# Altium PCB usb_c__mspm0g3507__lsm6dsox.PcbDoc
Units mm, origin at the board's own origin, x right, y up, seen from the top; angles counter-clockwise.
Board outline 68 x 40 mm, 2 copper layers (Top, Bottom), stack 0 mm thick; 37 components, 30 nets, 196 pads, 72 vias.
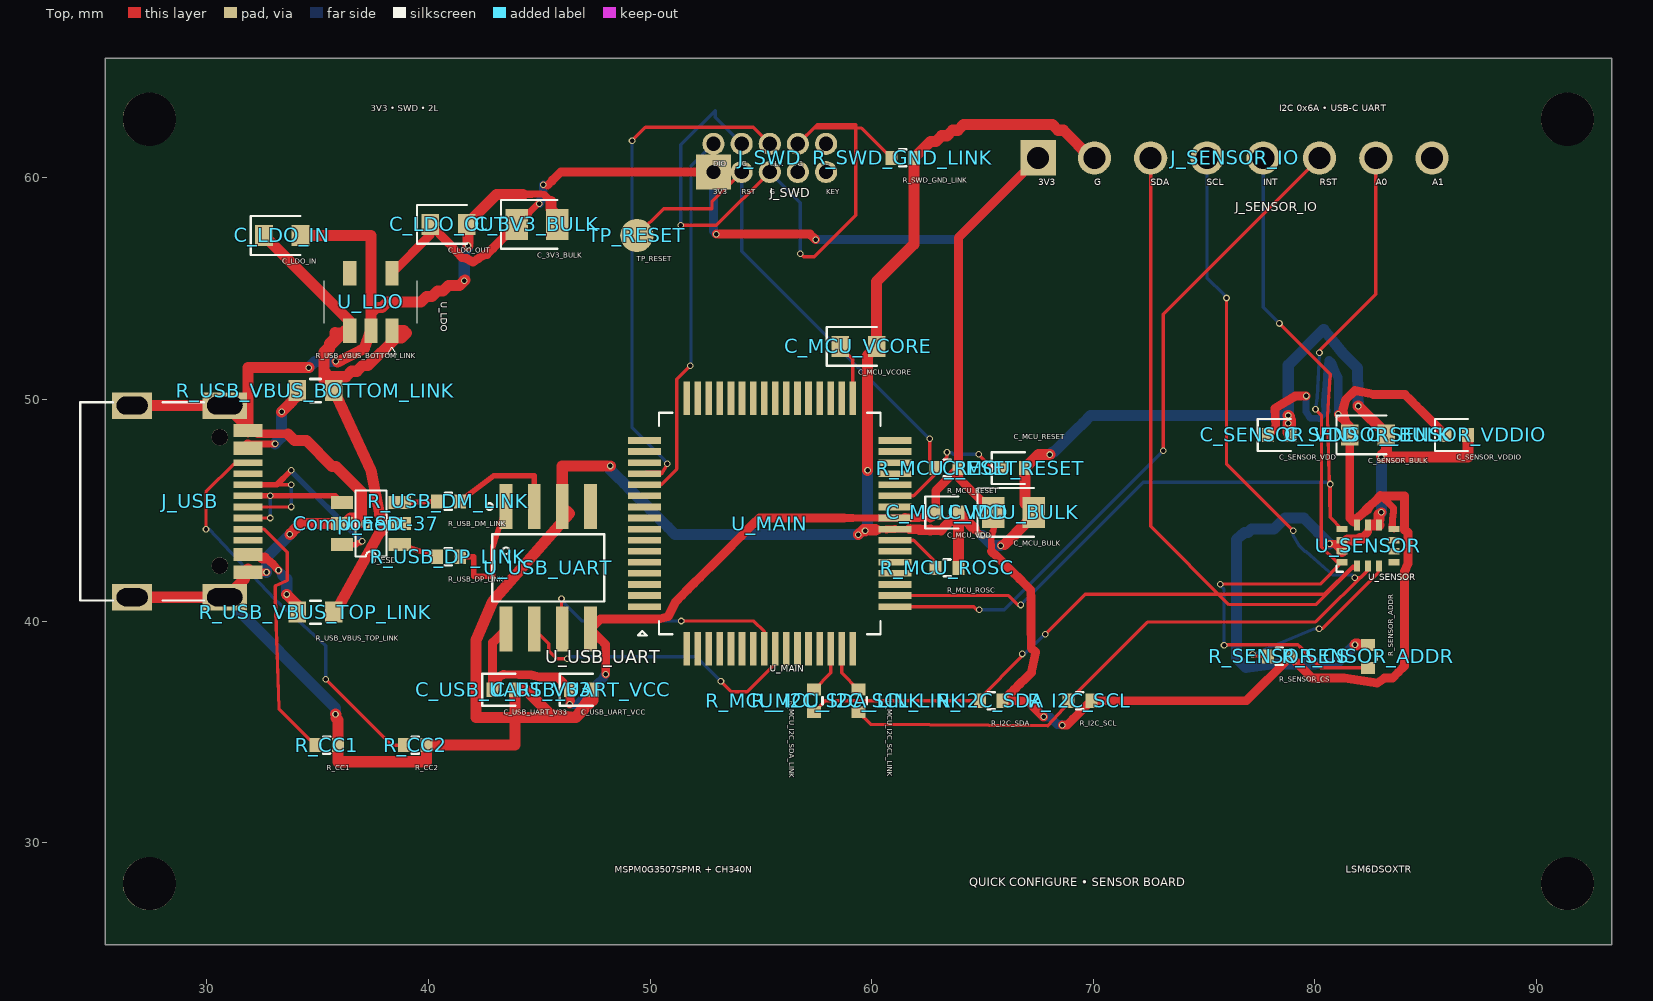
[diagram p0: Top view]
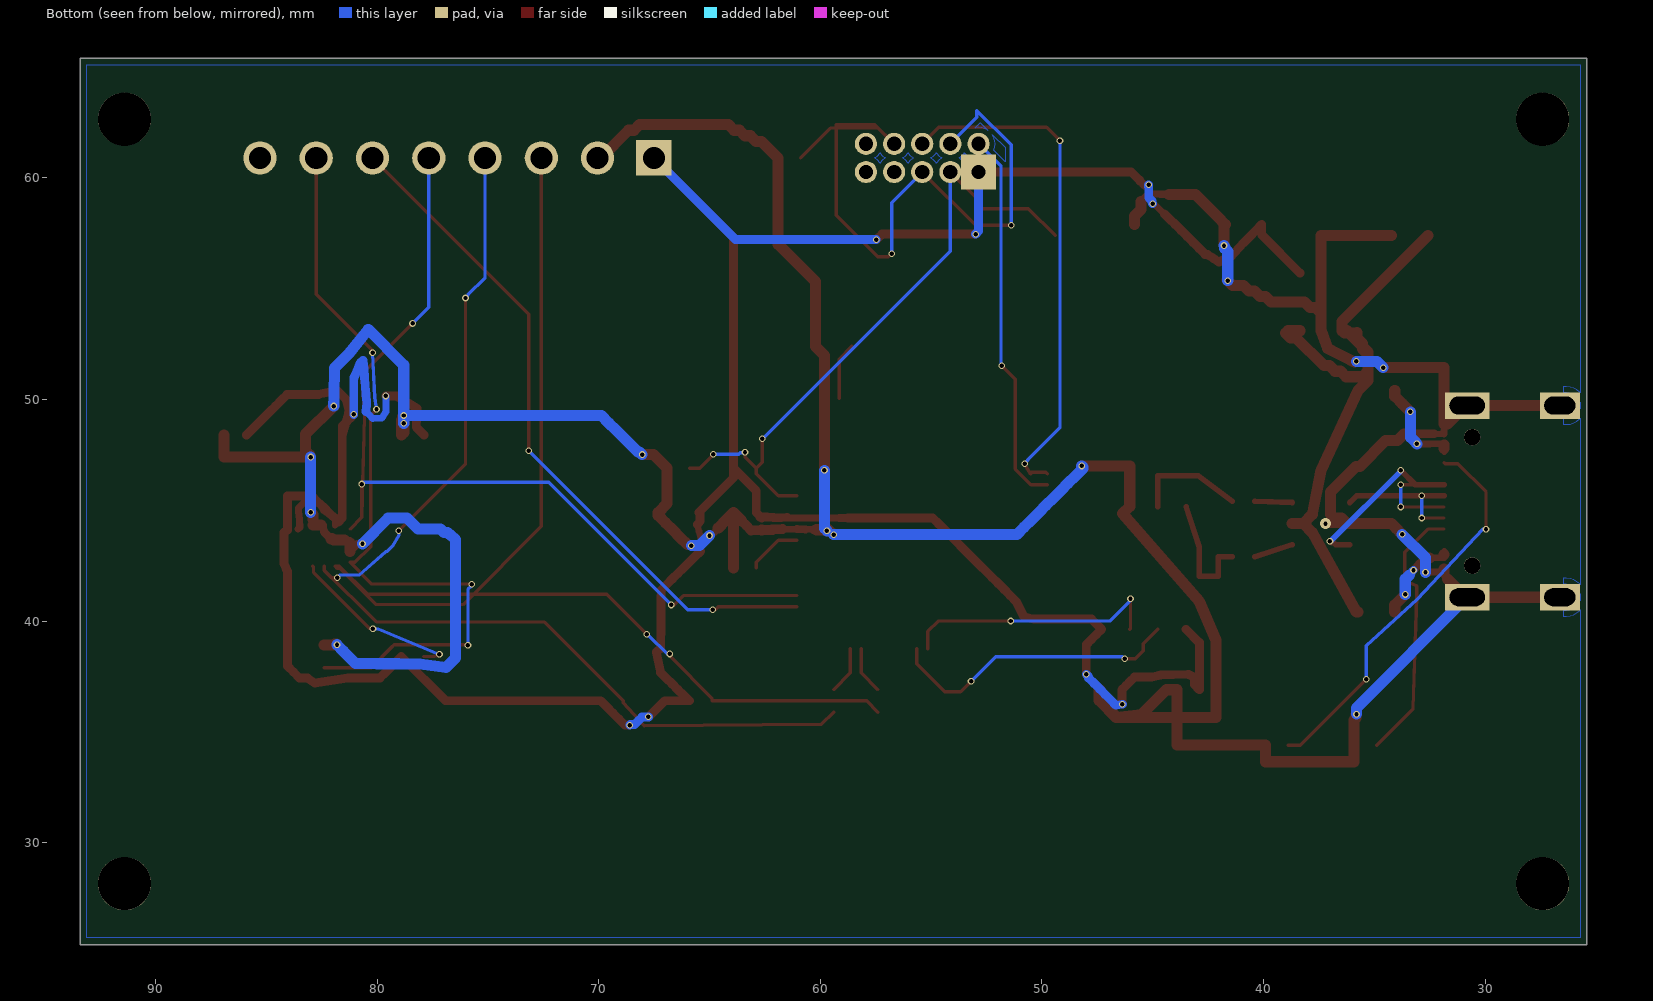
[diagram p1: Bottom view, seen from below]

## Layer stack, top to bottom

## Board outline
25.4,65.4 93.4,65.4 93.4,25.4 25.4,25.4

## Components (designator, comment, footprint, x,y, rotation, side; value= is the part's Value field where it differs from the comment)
C_3V3_BULK "" TSCIRCUIT-2.8500x1.4000mm 44.9,57.9 r0 top
C_LDO_IN "" TSCIRCUIT-2.4500x0.9500mm 33.4,57.4 r0 top
C_LDO_OUT "" TSCIRCUIT-2.4500x0.9500mm 40.9,57.9 r0 top
C_MCU_BULK "" TSCIRCUIT-2.8500x1.4000mm 66.4,44.9 r0 top
C_MCU_RESET "" TSCIRCUIT-1.5600x0.6400mm 66.4,46.9 r0 top
C_MCU_VCORE "" TSCIRCUIT-2.4500x0.9500mm 59.4,52.4 r0 top
C_MCU_VDD "" TSCIRCUIT-1.5600x0.6400mm 63.4,44.9 r0 top
C_SENSOR_BULK "" TSCIRCUIT-2.4500x0.9500mm 82.4,48.4 r0 top
C_SENSOR_VDD "" TSCIRCUIT-1.5600x0.6400mm 78.4,48.4 r0 top
C_SENSOR_VDDIO "" TSCIRCUIT-1.5600x0.6400mm 86.4,48.4 r0 top
C_USB_UART_V33 "" TSCIRCUIT-1.5600x0.6400mm 43.4,36.9 r0 top
C_USB_UART_VCC "" TSCIRCUIT-1.5600x0.6400mm 46.9,36.9 r0 top
Component-37 "" TSCIRCUIT-0.5000x0.5000mm 37.2,44.4 r0 top
J_SENSOR_IO "" TSCIRCUIT-19.2800x1.5000mm 76.4,60.9 r0 top
J_SWD "" TSCIRCUIT-6.0800x2.2700mm 55.4,60.9 r0 top
J_USB "" TSCIRCUIT-6.7732x9.8502mm 29.112,45.4 r90 top
R_CC1 "" TSCIRCUIT-1.5600x0.6400mm 35.4,34.4 r0 top
R_CC2 "" TSCIRCUIT-1.5600x0.6400mm 39.4,34.4 r0 top
R_I2C_SCL "" TSCIRCUIT-1.5600x0.6400mm 69.4,36.4 r0 top
R_I2C_SDA "" TSCIRCUIT-1.5600x0.6400mm 65.4,36.4 r0 top
R_MCU_I2C_SCL_LINK "" TSCIRCUIT-0.6400x1.5600mm 59.4,36.4 r270 top
R_MCU_I2C_SDA_LINK "" TSCIRCUIT-0.6400x1.5600mm 57.4,36.4 r270 top
R_MCU_RESET "" TSCIRCUIT-1.5600x0.6400mm 63.4,46.9 r0 top
R_MCU_ROSC "" TSCIRCUIT-1.5600x0.6400mm 63.4,42.4 r0 top
R_SENSOR_ADDR "" TSCIRCUIT-0.6400x1.5600mm 82.4,38.4 r90 top
R_SENSOR_CS "" TSCIRCUIT-1.5600x0.6400mm 78.4,38.4 r0 top
R_SWD_GND_LINK "" TSCIRCUIT-1.5600x0.6400mm 61.4,60.9 r0 top
R_USB_DM_LINK "" TSCIRCUIT-1.5600x0.6400mm 40.9,45.4 r0 top
R_USB_DP_LINK "" TSCIRCUIT-1.5600x0.6400mm 40.9,42.9 r0 top
R_USB_VBUS_BOTTOM_LINK "" TSCIRCUIT-2.4500x0.9500mm 34.9,50.4 r0 top
R_USB_VBUS_TOP_LINK "" TSCIRCUIT-2.4500x0.9500mm 34.9,40.4 r0 top
TP_RESET "" TSCIRCUIT-1.5000x1.5000mm 49.4,57.4 r0 top
U_ESD "" TSCIRCUIT-3.6000x2.5000mm 37.4,44.4 r0 top
U_LDO "" TSCIRCUIT-2.5000x3.7000mm 37.4,54.4 r270 top
U_MAIN "" TSCIRCUIT-12.8000x12.8000mm 55.4,44.4 r0 top
U_SENSOR "" TSCIRCUIT-2.8499x2.3500mm 82.4,43.4 r0 top
U_USB_UART "" TSCIRCUIT-4.3840x7.5712mm 45.4,42.4 r0 top

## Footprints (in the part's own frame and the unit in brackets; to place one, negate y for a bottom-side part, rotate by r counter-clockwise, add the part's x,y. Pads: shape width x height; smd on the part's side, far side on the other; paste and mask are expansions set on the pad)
TSCIRCUIT-0.5000x0.5000mm [mm]
TSCIRCUIT-0.6400x1.5600mm [mm]
  rect 0.54x0.64 smd: 1(-0.51,0) 2(0.51,0)
  silkscreen extent -0.15,-0.38 0.15,0.38
TSCIRCUIT-1.5000x1.5000mm [mm]
  round 1.5 smd: 1(0,0)
TSCIRCUIT-1.5600x0.6400mm [mm]
  rect 0.54x0.64 smd: 1(-0.51,0) 2(0.51,0)
  silkscreen extent -0.98,-0.72 0.51,0.72
TSCIRCUIT-2.4500x0.9500mm [mm]
  rect 0.8x0.95 smd: 1(-0.825,0) 2(0.825,0)
  silkscreen extent -1.42,-0.87 0.82,0.87
TSCIRCUIT-2.5000x3.7000mm [mm]
  rect 1.1x0.6 smd: 1(1.3,0.95) 2(1.3,0) 3(1.3,-0.95) 4(-1.3,-0.95) 5(-1.3,0.95)
  silkscreen extent -0.95,-2.1 2.35,2.1
TSCIRCUIT-2.8499x2.3500mm [mm]
  rect 0.5x0.28 smd: 1(-1.175,-0.75) 2(-1.175,-0.25) 3(-1.175,0.25) 4(-1.175,0.75) 8(1.175,0.75) 9(1.175,0.25) 10(1.175,-0.25) 11(1.175,-0.75)
  rect 0.28x0.5 smd: 5(-0.5,0.925) 6(0,0.925) 7(0.5,0.925) 12(0.5,-0.925) 13(0,-0.925) 14(-0.5,-0.925)
  silkscreen extent -1.42,-1.17 -1.14,-0.89
TSCIRCUIT-2.8500x1.4000mm [mm]
  rect 1.025x1.4 smd: 1(-0.913,0) 2(0.913,0)
  silkscreen extent -1.62,-1.1 0.91,1.1
TSCIRCUIT-3.6000x2.5000mm [mm]
  rect 1x0.6 smd: 1(-1.3,-0.95) 2(-1.3,0) 3(-1.3,0.95) 4(1.3,0.95) 5(1.3,0) 6(1.3,-0.95)
  silkscreen extent -0.7,-1.49 0.7,1.49
TSCIRCUIT-4.3840x7.5712mm [mm]
  rect 0.574x2.036 smd: 1(-1.905,2.768) 2(-0.635,2.768) 3(0.635,2.768) 4(1.905,2.768) 5(1.905,-2.768) 6(0.635,-2.768) 7(-0.635,-2.768) 8(-1.905,-2.768)
  silkscreen extent -2.79,-1.52 2.53,2.92
TSCIRCUIT-6.0800x2.2700mm [mm]
  rect 1.6x1.6 hole 0.65: 1(-2.54,-0.635)
  round 1 hole 0.65: 2(-2.54,0.635) 3(-1.27,0.635) 4(0,0.635) 5(1.27,0.635) 6(2.54,0.635) 7(2.54,-0.635) 8(1.27,-0.635) 9(0,-0.635) 10(-1.27,-0.635)
TSCIRCUIT-6.7732x9.8502mm [mm]
  rect 0.3x1.3 smd: 1(-3.35,-2.737) 2(-3.05,-2.737) 3(-2.55,-2.737) 4(-2.25,-2.737) 5(-1.75,-2.737) 6(-1.25,-2.737) 7(-0.75,-2.737) 8(-0.25,-2.737) 9(0.25,-2.737) 10(0.75,-2.737) 11(1.25,-2.737) 12(1.75,-2.737) 13(2.55,-2.737) 14(2.25,-2.737) 15(3.35,-2.737) 16(3.05,-2.737)
  rect 1.2x2 hole 0.8 slot 1.6 at 90 deg: 17(-4.325,-1.693) 18(4.325,-1.693)
  rect 1.2x1.8 hole 0.8 slot 1.4 at 90 deg: 19(4.325,2.487) 20(-4.325,2.487)
  round 0.75 hole 0.75 unplated: NPTH-1(-2.9,-1.468) NPTH-2(2.9,-1.468)
  silkscreen extent -4.47,-0.75 4.47,4.83
TSCIRCUIT-12.8000x12.8000mm [mm]
  rect 1.5x0.3 smd: 1(-5.65,-3.75) 2(-5.65,-3.25) 3(-5.65,-2.75) 4(-5.65,-2.25) 5(-5.65,-1.75) 6(-5.65,-1.25) 7(-5.65,-0.75) 8(-5.65,-0.25) 9(-5.65,0.25) 10(-5.65,0.75) 11(-5.65,1.25) 12(-5.65,1.75) 13(-5.65,2.25) 14(-5.65,2.75) 15(-5.65,3.25) 16(-5.65,3.75) 33(5.65,3.75) 34(5.65,3.25) 35(5.65,2.75) 36(5.65,2.25) 37(5.65,1.75) 38(5.65,1.25) 39(5.65,0.75) 40(5.65,0.25) 41(5.65,-0.25) 42(5.65,-0.75) 43(5.65,-1.25) 44(5.65,-1.75) 45(5.65,-2.25) 46(5.65,-2.75) 47(5.65,-3.25) 48(5.65,-3.75)
  rect 0.3x1.5 smd: 17(-3.75,5.65) 18(-3.25,5.65) 19(-2.75,5.65) 20(-2.25,5.65) 21(-1.75,5.65) 22(-1.25,5.65) 23(-0.75,5.65) 24(-0.25,5.65) 25(0.25,5.65) 26(0.75,5.65) 27(1.25,5.65) 28(1.75,5.65) 29(2.25,5.65) 30(2.75,5.65) 31(3.25,5.65) 32(3.75,5.65) 49(3.75,-5.65) 50(3.25,-5.65) 51(2.75,-5.65) 52(2.25,-5.65) 53(1.75,-5.65) 54(1.25,-5.65) 55(0.75,-5.65) 56(0.25,-5.65) 57(-0.25,-5.65) 58(-0.75,-5.65) 59(-1.25,-5.65) 60(-1.75,-5.65) 61(-2.25,-5.65) 62(-2.75,-5.65) 63(-3.25,-5.65) 64(-3.75,-5.65)
  silkscreen extent -5.95,-5.05 5,5
TSCIRCUIT-19.2800x1.5000mm [mm]
  rect 1.6x1.6 hole 1: 1(-8.89,0)
  round 1.5 hole 1: 2(-6.35,0) 3(-3.81,0) 4(-1.27,0) 5(1.27,0) 6(3.81,0) 7(6.35,0) 8(8.89,0)

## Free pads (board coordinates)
  round 2.4 hole 2.4 unplated: NPTH-3(27.4,28.15) NPTH-4(91.4,28.15) NPTH-5(27.4,62.65) NPTH-6(91.4,62.65)

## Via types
v1: diameter 0.3, hole 0.2, Top to Bottom, 71 vias
v2: diameter 0.5, hole 0.2, Top to Bottom, 1 vias

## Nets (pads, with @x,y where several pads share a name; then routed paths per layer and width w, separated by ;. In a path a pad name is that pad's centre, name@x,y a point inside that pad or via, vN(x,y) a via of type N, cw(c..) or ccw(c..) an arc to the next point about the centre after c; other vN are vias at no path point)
".J_SWD > .pin2 to .U_MAIN > .pin12": J_SWD.2 U_MAIN.12 | length 17.1
  Top w0.15: U_MAIN.12 50.494,46.15 51.203,46.858 51.203,50.912 v1(51.815,51.524)
  Bottom w0.15: v1(51.815,51.524) 51.844,51.553 51.844,51.59 51.844,60.519 J_SWD.2
".J_SWD > .pin4 to .U_MAIN > .pin13": J_SWD.4 U_MAIN.13 | length 23.4
  Top w0.15: v1(49.185,61.676) 49.203,61.694 49.789,62.28 49.959,62.28 54.655,62.28 J_SWD.4 ; U_MAIN.13 49.819,46.719 50.52,46.719 50.509,46.646 50.708,46.977 v1(50.776,47.106)
  Bottom w0.15: v1(49.185,61.676) 49.185,48.726 50.633,47.277 50.633,47.249 v1(50.776,47.106)
".U_MAIN > .pin42 to .R_MCU_ROSC > .pin1": R_MCU_ROSC.1 U_MAIN.42 | length 2.5
  Top w0.15: U_MAIN.42 61.89,43.65 62.89,42.65 R_MCU_ROSC.1
GND: C_3V3_BULK.2 C_LDO_IN.2 C_LDO_OUT.2 C_MCU_BULK.2 C_MCU_RESET.2 C_MCU_VCORE.2 C_MCU_VDD.2 C_SENSOR_BULK.2 C_SENSOR_VDD.2 C_SENSOR_VDDIO.2 C_USB_UART_V33.2 C_USB_UART_VCC.2 J_SENSOR_IO.2 J_USB.1 J_USB.2 J_USB.15 J_USB.16 J_USB.17 J_USB.18 J_USB.19 J_USB.20 R_CC1.2 R_CC2.2 R_MCU_ROSC.2 R_SENSOR_ADDR.2 R_SWD_GND_LINK.2 U_ESD.2 U_LDO.2 U_MAIN.41 U_SENSOR.2 U_SENSOR.3 U_SENSOR.6 U_SENSOR.7 U_USB_UART.3 | length 214.3
  Top w0.275: J_USB.16 J_USB.16@32.299,48.45
  Top w0.28: 81.085,43.29 U_SENSOR.2 ; 81.225,43.51 U_SENSOR.3 U_SENSOR.3@81.475,43.65 ; U_SENSOR.6@82.4,44.075 U_SENSOR.6 U_SENSOR.6@82.54,44.325 ; U_SENSOR.7 82.9,44.575
  Top w0.3: J_USB.1@31.699,41.9 J_USB.1 J_USB.1@31.849,42.2 ; J_USB.15@31.699,48.9 J_USB.15 ; J_USB.16@31.849,48.6 J_USB.15 ; J_USB.15@31.849,48.9 J_USB.15 ; 60.113,44.15 60.582,44.15 U_MAIN.41 61.144,44.15 61.238,44.15 61.331,44.15 61.425,44.15 61.519,44.15 61.613,44.15 U_MAIN.41@61.706,44.15 ; 60.3,44.12 U_MAIN.41@60.675,44.135
  Top w0.32: J_USB.2 31.987,42.212 32.336,42.207 J_USB.2@32.499,42.204
  Top w0.325: J_USB.16 J_USB.16@31.849,48.6 ; 44.268,59.258 44.669,59.264 45.071,59.269 45.223,59.237 45.518,58.943 ; 64.605,44.205 64.605,44.178 64.779,44.004 v1(65.001,43.858) ; v1(65.819,43.4) v1@65.847,43.447
  Top w0.35: 32.499,42.204 v1(32.686,42.201) ; v1(35.806,51.722) v1@35.9,51.7 ; v1(80.661,43.487) 80.897,43.478 81.085,43.29
  Top w0.36: U_MAIN.41@60.675,44.135 U_MAIN.41
  Top w0.375: J_USB.16@32.299,48.45 32.749,48.45 33.199,48.45 ; v1@65.847,43.447 65.993,43.447 ; 82.087,43.713 82.4,44.025 U_SENSOR.6@82.4,44.075
  Top w0.4: 33.199,48.45 33.649,48.45 ; 36.6,44.4 37.2,44.4 ; 60.175,44.12 60.3,44.12
  Top w0.437: 63.119,44.087 63.338,44.306 63.556,44.525
  Top w0.45: U_MAIN.41@61.706,44.15 62.177,44.129 ; 62.648,44.108 63.119,44.087 ; v1@82.9,44.808 v1(83.003,44.91)
  Top w0.475: v1(59.397,43.902) 59.401,43.907 59.645,44.15 60.113,44.15 ; 62.177,44.129 62.648,44.108
  Top w0.5: J_USB.20 J_USB.17 ; J_USB.19 J_USB.18 ; J_USB.17 30.874,41.075 31.474,41.675 31.699,41.9 ; J_USB.18 30.874,49.725 31.474,49.125 31.699,48.9 ; J_USB.1@31.849,42.2 J_USB.2 ; 31.849,48.9 31.849,51.439 v1(34.596,51.439) ; 33.649,48.45 33.949,48.15 34.483,48.15 35.65,46.983 35.817,46.983 36.983,45.817 36.983,44.817 36.817,44.65 36.483,44.65 36.233,44.4 U_ESD.2 35.632,44.4 35.164,44.4 34.697,44.4 34.229,44.4 34.007,44.178 v1@33.784,43.955 ; v1(33.742,43.914) v1@33.783,43.955 ; C_LDO_IN.2 37.4,57.4 U_LDO.2 ; v1(35.8,35.8) 35.83,35.77 35.83,35.617 35.91,35.537 R_CC1.2 35.91,33.65 39.91,33.65 R_CC2.2 43.91,34.4 C_USB_UART_V33.2 44.385,36.9 45.495,35.79 46.65,35.65 ; v1@35.9,51.7 36.3,51.9 36.7,52.1 37.1,52.3 U_LDO.2 ; v1(41.611,55.365) 41.646,55.4 41.65,55.4 41.4,55.15 40.9,55.15 40.65,54.9 40.4,54.9 40.15,54.65 39.9,54.65 39.65,54.4 38.15,54.4 37.9,54.15 37.65,54.15 37.4,53.9 U_LDO.2 ; v1(41.781,56.946) 41.781,57.395 41.781,57.844 C_LDO_OUT.2 42.06,58.235 42.395,58.571 42.729,58.906 43.064,59.242 43.465,59.247 43.867,59.253 44.268,59.258 ; 45.518,58.943 45.518,58.57 45.813,58.275 C_3V3_BULK.2@45.813,57.9 ; v1(48.2,47) 46.035,47 U_USB_UART.3 46.353,44.85 42.9,40.9 42.15,39.15 42.15,35.65 46.65,35.65 ; v1(59.7,44.075) 59.745,44.12 60.05,44.12 60.175,44.12 ; v1(59.813,46.799) 59.817,46.803 59.817,46.819 59.817,51.992 C_MCU_VCORE.2 60.225,52.887 60.225,53.374 60.225,53.86 60.225,54.347 60.225,54.834 60.225,55.321 61.91,57.006 R_SWD_GND_LINK.2 62.247,61.237 62.584,61.574 62.65,61.64 62.65,61.65 62.9,61.65 63.15,61.9 63.4,61.9 63.65,62.15 63.9,62.15 64.15,62.4 68.15,62.4 68.4,62.15 68.65,62.15 69.9,60.9 J_SENSOR_IO.2 ; 63.556,44.525 63.66,44.65 C_MCU_VDD.2 ; R_MCU_ROSC.2 C_MCU_VDD.2 ; 64.605,44.205 64.257,44.553 C_MCU_VDD.2 ; 65.993,43.447 66.323,43.776 66.653,44.106 66.983,44.436 67.312,44.766 C_MCU_BULK.2 66.91,45.303 C_MCU_RESET.2 67.217,47.206 67.523,47.513 67.783,47.513 v1(68.043,47.513) ; v1(78.8,48.925) 78.8,48.893 78.8,48.51 C_SENSOR_VDD.2 78.91,48.734 78.91,49.067 78.852,49.126 78.852,49.223 v1(78.8,49.275) ; U_SENSOR.2 81.225,43.29 81.225,43.51 ; 81.475,43.65 81.971,43.65 82.043,43.723 82.087,43.713 ; v1(81.813,38.929) 81.842,38.958 81.92,38.958 81.968,38.91 R_SENSOR_ADDR.2 ; v1(81.958,49.702) 83.225,48.435 C_SENSOR_BULK.2 ; U_SENSOR.6@82.54,44.325 82.76,44.325 U_SENSOR.7 ; 82.9,44.575 v1@82.9,44.808 ; v1(83,47.4) 83.029,47.429 83.029,47.481 83.225,47.678 83.225,48.039 C_SENSOR_BULK.2 ; C_SENSOR_VDDIO.2 86.91,47.4 83.225,47.4 C_SENSOR_BULK.2 ; 46.65,35.65 47.364,36.666 47.364,36.854 C_USB_UART_VCC.2 47.41,36.41 46.65,35.65
  Bottom w0.5: J_USB.17 35.8,36.081 v1(35.8,35.8) ; v1(32.686,42.201) 32.686,42.858 v1(33.742,43.914) ; v1(34.596,51.439) v1@34.645,51.488 ; v1@34.647,51.488 34.88,51.722 35.343,51.722 v1(35.806,51.722) ; v1(41.611,55.365) 41.611,55.801 41.611,56.236 41.611,56.672 41.747,56.807 41.747,56.881 v1(41.781,56.946) ; v1(48.2,47) 48.152,46.952 48.152,46.883 48.484,46.551 48.815,46.22 49.146,45.889 49.477,45.558 49.808,45.227 50.139,44.895 50.471,44.564 50.802,44.233 51.133,43.902 51.619,43.902 52.105,43.902 52.591,43.902 53.077,43.902 53.564,43.902 54.05,43.902 54.536,43.902 55.022,43.902 55.508,43.902 55.994,43.902 56.48,43.902 56.966,43.902 57.452,43.902 57.938,43.902 58.425,43.902 58.911,43.902 v1(59.397,43.902) ; v1(59.7,44.075) 59.813,44.188 v1(59.813,46.799) ; v1(65.001,43.858) 65.459,43.4 v1(65.819,43.4) ; v1(68.043,47.513) 68.16,47.63 68.233,47.63 68.562,47.959 68.891,48.288 69.22,48.617 69.549,48.946 69.878,49.275 70.373,49.275 70.869,49.275 71.365,49.275 71.86,49.275 72.356,49.275 72.852,49.275 73.348,49.275 73.843,49.275 74.339,49.275 74.835,49.275 75.33,49.275 75.826,49.275 76.322,49.275 76.817,49.275 77.313,49.275 77.809,49.275 78.304,49.275 v1(78.8,49.275) ; v1(78.8,48.925) 78.8,51.55 80.4,53.15 81.267,52.079 81.593,51.754 81.918,51.428 81.928,50.997 81.938,50.565 81.948,50.134 v1(81.958,49.702) ; v1(80.661,43.487) 79.499,44.65 78.65,44.65 78.15,44.15 77.15,44.15 76.987,43.987 76.82,43.987 76.741,43.908 76.704,43.908 76.466,43.67 76.466,38.334 76.9,37.9 78.075,38.069 78.557,38.07 79.039,38.071 79.521,38.072 80.003,38.073 80.485,38.075 80.968,38.076 81.249,38.36 81.531,38.645 v1(81.813,38.929) ; v1(83,47.4) 83,44.913 v1(83.003,44.91)
MAIN_RESET: C_MCU_RESET.1 J_SWD.10 R_MCU_RESET.1 TP_RESET.1 U_MAIN.38 | length 29.3
  Top w0.15: TP_RESET.1 50.606,58.606 52.789,58.606 52.789,58.924 J_SWD.10 ; U_MAIN.38 61.889,45.65 62.89,46.651 R_MCU_RESET.1 ; v1(62.618,48.222) 62.618,47.172 R_MCU_RESET.1 ; v1(63.4,47.62) 63.4,47.41 R_MCU_RESET.1 ; v1(64.836,47.525) 64.882,47.479 64.882,47.459 65.442,46.9 C_MCU_RESET.1
  Bottom w0.15: J_SWD.10 54.13,56.685 62.519,48.296 62.544,48.296 v1(62.618,48.222) ; v1(63.4,47.62) 63.425,47.595 63.616,47.595 63.686,47.525 v1(64.836,47.525)
MCU_I2C_SCL_LOCAL: R_MCU_I2C_SCL_LINK.1 U_MAIN.50 | length 2.2
  Top w0.15: U_MAIN.50 58.65,37.66 R_MCU_I2C_SCL_LINK.1
MCU_I2C_SDA_LOCAL: R_MCU_I2C_SDA_LINK.1 U_MAIN.51 | length 2.2
  Top w0.15: R_MCU_I2C_SDA_LINK.1 58.15,37.66 U_MAIN.51
MSPM0_VCORE: C_MCU_VCORE.1 U_MAIN.32 | length 2.6
  Top w0.15: C_MCU_VCORE.1 59.15,51.825 U_MAIN.32
SENSOR_ADDR0: J_SENSOR_IO.7 R_SENSOR_ADDR.1 U_SENSOR.1 | length 35.6
  Top w0.15: v1(75.726,41.668) 80.243,41.668 U_SENSOR.1 81.012,42.648 80.291,43.358 80.299,49.282 v1(80.028,49.553) ; v1(75.902,38.915) 75.917,38.93 76.081,38.93 79.224,38.93 79.307,38.862 80.264,37.89 R_SENSOR_ADDR.1 ; v1(80.207,52.105) 80.204,52.104 80.204,52.205 82.75,54.751 J_SENSOR_IO.7
  Bottom w0.15: v1(75.726,41.668) 75.733,41.62 75.733,41.593 75.902,41.424 v1(75.902,38.915) ; v1(80.028,49.553) 80.103,50.085 v1(80.207,52.105)
SENSOR_ADDR1: J_SENSOR_IO.8
SENSOR_CS: R_SENSOR_CS.1 U_SENSOR.12 | length 8
  Top w0.15: v1(77.189,38.495) 77.231,38.425 77.401,38.425 77.426,38.4 R_SENSOR_CS.1 ; v1(80.189,39.657) 80.344,39.661 82.872,42.189 82.872,42.447 U_SENSOR.12
  Bottom w0.15: v1(77.189,38.495) 79.951,39.644 80.17,39.644 v1(80.189,39.657)
SENSOR_INT: J_SENSOR_IO.5 U_MAIN.47 U_SENSOR.4 | length 42.6
  Top w0.15: U_MAIN.47 66.175,41.15 66.617,40.708 66.702,40.708 v1(66.72,40.726) ; v1(78.402,53.43) 80.694,51.137 80.568,49.25 80.695,44.68 U_SENSOR.4 80.69,44.685 v1(80.69,46.183)
  Bottom w0.15: v1(66.72,40.726) 72.252,46.258 80.481,46.258 80.615,46.258 v1(80.69,46.183) ; J_SENSOR_IO.5 77.67,54.164 78.387,53.447 v1(78.402,53.43)
SENSOR_RESET: J_SENSOR_IO.6 U_MAIN.48 | length 31.3
  Top w0.15: U_MAIN.48 64.601,40.65 64.742,40.51 64.853,40.51 v1(64.855,40.512) ; v1(73.162,47.685) 73.162,53.852 J_SENSOR_IO.6
  Bottom w0.15: v1(64.855,40.512) 65.989,40.512 73.132,47.655 v1(73.162,47.685)
SENSOR_SCL: J_SENSOR_IO.4 R_I2C_SCL.1 R_MCU_I2C_SCL_LINK.2 U_SENSOR.13 | length 49.6
  Top w0.15: R_MCU_I2C_SCL_LINK.2 59.952,35.338 67.95,35.275 68.89,36.304 R_I2C_SCL.1 72.445,39.955 80.033,39.959 82.402,42.318 U_SENSOR.13 82.394,42.469 82.394,42.281 82.089,41.976 v1(81.793,41.96) ; v1(76.013,54.58) 76.013,47.083 v1(79.018,44.078)
  Bottom w0.15: J_SENSOR_IO.4 75.13,55.494 75.904,54.721 75.904,54.689 v1(76.013,54.58) ; v1(79.018,44.078) 79.014,43.873 79.313,43.375 79.537,43.15 79.613,43.129 80.817,42.074 81.693,42.076 81.779,41.99 v1(81.793,41.96)
SENSOR_SDA: J_SENSOR_IO.3 R_I2C_SDA.1 R_MCU_I2C_SDA_LINK.2 U_SENSOR.14 | length 55.4
  Top w0.15: R_MCU_I2C_SDA_LINK.2 57.91,36.4 R_I2C_SDA.1 64.89,36.514 66.754,38.378 66.754,38.433 v1(66.799,38.515) ; v1(67.825,39.398) 69.631,41.204 80.431,41.204 81.706,42.471 U_SENSOR.14 81.814,42.389 81.686,42.389 80.043,40.746 76.123,40.746 72.59,44.279 J_SENSOR_IO.3
  Bottom w0.15: v1(66.799,38.515) 66.918,38.515 67.743,39.34 67.767,39.34 v1(67.825,39.398)
swd-ground-1-to-2: J_SWD.3 J_SWD.5 J_SWD.9 R_SWD_GND_LINK.1 | length 32.5
  Top w0.15: v1(51.387,57.869) 51.398,57.858 52.993,57.858 J_SWD.9 ; v1(56.78,56.583) 56.922,56.441 57.403,56.441 59.277,58.315 59.277,62.405 57.54,62.405 J_SWD.5 57.382,62.247 59.375,62.247 59.543,62.247 R_SWD_GND_LINK.1
  Bottom w0.15: v1(51.387,57.869) 51.387,61.491 52.934,63.038 52.934,62.731 J_SWD.3 ; J_SWD.9 56.78,58.885 v1(56.78,56.583)
UART_MSP_RX: U_MAIN.57 U_USB_UART.6 | length 12
  Top w0.15: v1(46,41) 46,39.667 U_USB_UART.6 ; v1(51.4,40.001) 51.43,40.001 51.431,40 54.679,40 55.15,39.529 U_MAIN.57
  Bottom w0.15: v1(46,41) 46.033,40.967 46.033,40.901 46.933,40.001 v1(51.4,40.001)
UART_MSP_TX: U_MAIN.56 U_USB_UART.7 | length 13.5
  Top w0.15: U_USB_UART.7 45.425,38.972 45.425,38.649 45.781,38.293 v1(46.257,38.293) ; v1(53.196,37.282) 53.298,37.18 53.672,36.806 54.392,36.806 55.65,38.064 U_MAIN.56
  Bottom w0.15: v1(46.257,38.293) 46.377,38.395 46.409,38.395 52.083,38.395 v1(53.196,37.282)
usb-dm-device: R_USB_DM_LINK.1 U_ESD.4 | length 1.7
  Top w0.25: U_ESD.4 R_USB_DM_LINK.1
usb-dm-port-tie: J_USB.7 J_USB.9 U_ESD.3 | length 7.4
  Top w0.15: J_USB.7 v1(32.85,44.65) ; J_USB.9 v1(32.85,45.65)
  Top w0.25: J_USB.9 35.8,45.65 U_ESD.3
  Bottom w0.15: v1(32.85,44.65) v1(32.85,45.65)
usb-dm-uart: R_USB_DM_LINK.2 U_USB_UART.2 | length 5.1
  Top w0.25: R_USB_DM_LINK.2 42.95,46.55 44.765,46.55 U_USB_UART.2
usb-dp-device: R_USB_DP_LINK.1 U_ESD.6 | length 1.8
  Top w0.25: U_ESD.6 R_USB_DP_LINK.1
usb-dp-port-tie: J_USB.8 J_USB.10 U_ESD.1 | length 12.6
  Top w0.15: J_USB.8 v1(33.8,45.15) ; J_USB.10 v1(33.8,46.15)
  Top w0.25: J_USB.10 33.15,46.15 v1(33.8,46.8) ; U_ESD.1 36.746,43.45 36.82,43.523 36.923,43.523 v1(37,43.6)
  Bottom w0.15: v1(33.8,45.15) v1(33.8,46.15)
  Bottom w0.25: v1(33.8,46.8) 33.8,46.774 36.974,43.6 v1(37,43.6)
usb-dp-uart: R_USB_DP_LINK.2 U_USB_UART.1 | length 5.6
  Top w0.25: R_USB_DP_LINK.2 42.05,42.9 42.05,42.03 42.9,42.03 42.9,43.35 U_USB_UART.1
USB_CC1: J_USB.6 R_CC1.1 | length 11.9
  Top w0.15: J_USB.6 32.578,44.15 33.624,43.104 33.624,41.836 33.075,41.575 33.075,41.125 33.25,36.04 R_CC1.1
USB_CC2: J_USB.12 R_CC2.1 | length 18
  Top w0.15: v1(29.956,44.138) 29.956,45.827 31.235,47.106 31.805,47.106 J_USB.12 ; v1(35.359,37.374) 35.37,37.363 38.333,34.4 R_CC2.1
  Bottom w0.15: v1(29.956,44.138) 30.099,44.138 33.051,40.984 35.359,38.878 v1(35.359,37.374)
USB_VBUS_BOTTOM_LOCAL: J_USB.13 J_USB.14 R_USB_VBUS_BOTTOM_LINK.1 | length 4.4
  Top w0.3: J_USB.14 J_USB.14@31.849,47.8 ; J_USB.13 31.893,47.994 32.286,47.994 J_USB.13@32.499,47.994
  Top w0.325: 32.499,47.994 32.68,47.994 v1(33.073,47.994)
  Top w0.475: J_USB.13@31.849,47.8 J_USB.13
  Top w0.5: v1(33.372,49.443) 33.395,49.466 33.735,49.806 34.075,50.146 R_USB_VBUS_BOTTOM_LINK.1
  Bottom w0.5: v1(33.073,47.994) 33.124,48.045 33.124,48.047 33.372,48.295 33.372,48.678 33.372,49.06 v1(33.372,49.443)
USB_VBUS_TOP_LOCAL: J_USB.3 J_USB.4 R_USB_VBUS_TOP_LINK.1 | length 4.1
  Top w0.3: J_USB.4 31.849,43 J_USB.3 J_USB.3@31.946,42.868 ; J_USB.3@32.037,42.85 32.13,42.85 32.224,42.85 32.318,42.85 32.411,42.85 J_USB.3@32.499,42.85
  Top w0.301: J_USB.3@31.946,42.868 J_USB.3@32.037,42.85
  Top w0.375: 32.599,42.85 32.64,42.852 32.962,42.587 v1(33.23,42.29)
  Top w0.5: 32.499,42.85 32.505,42.85 32.599,42.85 ; v1(33.601,41.2) 34.075,40.726 R_USB_VBUS_TOP_LINK.1
  Bottom w0.375: v1(33.23,42.29) 33.407,42.08
  Bottom w0.5: 33.407,42.08 33.6,41.888 33.601,41.887 v1(33.601,41.2)
VBUS5: C_LDO_IN.1 R_USB_VBUS_BOTTOM_LINK.2 R_USB_VBUS_TOP_LINK.2 U_ESD.5 U_LDO.1 U_LDO.3 | length 29.8
  Top w0.5: C_LDO_IN.1 36.45,53.525 U_LDO.3 ; R_USB_VBUS_TOP_LINK.2 35.8,40.4 37.8,44 U_ESD.5@38.2,44.4 ; U_LDO.1 38.85,53.1 38.9,53.1 39,53 38.775,52.775 38.525,52.775 37.275,51.525 37.025,51.525 36.775,51.275 36.525,51.275 36.275,51.025 35.525,51.025 35.275,51.275 35.275,52.025 35.525,52.275 35.525,52.525 35.775,52.775 35.775,53.025 35.8,53 36.35,53 U_LDO.3 ; U_LDO.3 36.225,53.1 35.275,52.15 35.275,50.85 R_USB_VBUS_BOTTOM_LINK.2 37.4,46.8 37.8,44.8 U_ESD.5@38.2,44.4 ; U_ESD.5@38.2,44.4 U_ESD.5 U_ESD.5@38.2,44.4
VCC_3V3: C_3V3_BULK.1 C_LDO_OUT.1 C_MCU_BULK.1 C_MCU_VDD.1 C_SENSOR_BULK.1 C_SENSOR_VDD.1 C_SENSOR_VDDIO.1 C_USB_UART_V33.1 C_USB_UART_VCC.1 J_SENSOR_IO.1 J_SWD.1 R_I2C_SCL.2 R_I2C_SDA.2 R_MCU_RESET.2 R_SENSOR_CS.2 U_LDO.5 U_MAIN.40 U_SENSOR.5 U_SENSOR.8 U_USB_UART.5 U_USB_UART.8 | length 158.9
  Top w0.28: U_SENSOR.5@81.76,44.465 U_SENSOR.5 ; U_SENSOR.5 81.9,44.575 U_SENSOR.5
  Top w0.3: C_3V3_BULK.1@44.477,58.377 44.722,58.615 44.966,58.853 v1(45.001,58.839) ; v1(45.182,59.683) 45.181,59.674 45.363,59.662 ; 60.285,44.65 60.667,44.65 U_MAIN.40 ; U_MAIN.40@60.3,44.65 U_MAIN.40@60.34,44.65 ; U_MAIN.40@61.76,44.65 61.405,44.65 U_MAIN.40 ; 65.4,43.45 65.4,43.75 65.475,44.05 C_MCU_BULK.1@65.55,44.35 ; 82.157,44.825 81.9,44.65 ; U_MAIN.40@60.34,44.65 U_MAIN.40@60.695,44.65 ; U_MAIN.40@60.34,44.65 U_MAIN.40@60.695,44.65 ; U_MAIN.40@60.695,44.65 U_MAIN.40 ; U_MAIN.40@60.695,44.65 U_MAIN.40 ; 81.9,44.65 81.9,44.575 81.9,44.65
  Top w0.312: 59.137,44.65 59.52,44.65 59.902,44.65 60.285,44.65 ; 60.3,44.65 59.985,44.65 U_MAIN.40@60.34,44.65 ; 65.4,43.15 65.4,43.45
  Top w0.325: 82.157,44.825 82.414,45 82.65,45.4 82.95,45.7 83.55,45.1 83.55,44.95 83.498,44.566 83.497,44.228 U_SENSOR.8
  Top w0.344: U_MAIN.40@61.5,44.7 61.479,44.663 U_MAIN.40@61.791,44.672
  Top w0.35: 58.754,44.65 59.137,44.65 ; U_MAIN.40@61.5,44.7 61.807,44.675 62.115,44.65 U_MAIN.40@61.76,44.65
  Top w0.363: 45.363,59.662 45.564,59.863
  Top w0.375: U_MAIN.40@61.791,44.672 62.102,44.682
  Top w0.387: v1(46.369,36.243) 46.4,36.404
  Top w0.4: U_LDO.5 40.075,57.425 C_LDO_OUT.1 40.345,57.625 40.616,57.351 40.886,57.076 41.5,56.4 41.713,56.364 42,56.2 42.265,56.369 42.529,56.538 42.636,56.548 42.907,56.819 43.177,57.089 43.447,57.359 43.717,57.63 C_3V3_BULK.1 44.232,58.138 C_3V3_BULK.1@44.477,58.377 ; U_USB_UART.8 42.89,39.027 C_USB_UART_V33.1 43.126,37.136 43.126,37.47 43.4,37.6 44.638,37.564 45.05,37.47 45.435,37.47 45.82,37.47 46.01,37.28 46.2,37.09 C_USB_UART_VCC.1 46.39,36.657 46.39,36.414 46.4,36.404 ; 45.564,59.863 45.765,60.064 45.966,60.265 46.349,60.265 46.732,60.265 47.115,60.265 47.498,60.265 47.881,60.265 48.264,60.265 48.647,60.265 49.03,60.265 49.413,60.265 49.796,60.265 50.179,60.265 50.562,60.265 50.945,60.265 51.328,60.265 51.711,60.265 52.094,60.265 52.477,60.265 J_SWD.1 ; v1(48,37.6) 48,37.934 48,38.269 48,38.603 48,38.937 47.768,39.169 47.537,39.4 U_USB_UART.5 47.533,39.86 47.76,40.087 48.132,40.087 48.504,40.087 48.877,40.087 49.249,40.087 49.621,40.087 49.993,40.087 50.366,40.087 50.8,40.2 51.171,40.892 51.439,41.161 51.708,41.429 51.976,41.697 52.244,41.966 52.513,42.234 52.781,42.503 53.05,42.771 53.318,43.04 53.587,43.308 53.855,43.576 54.123,43.845 54.392,44.113 54.66,44.382 54.929,44.65 55.311,44.65 55.694,44.65 56.076,44.65 56.459,44.65 56.842,44.65 57.224,44.65 57.607,44.65 57.989,44.65 58.372,44.65 58.754,44.65 ; v1(52.988,57.464) 57.209,57.464 57.406,57.267 57.424,57.267 v1(57.476,57.215) ; 62.102,44.682 62.414,44.691 62.725,44.7 62.64,44.65 C_MCU_VDD.1 62.89,45.88 R_MCU_RESET.2 ; 65.4,43.15 65.667,42.899 65.919,42.65 66.171,42.4 66.423,42.15 66.675,41.9 66.927,41.65 67.179,41.4 67.185,41.012 67.19,40.624 67.192,40.255 67.194,39.885 67.196,39.516 67.198,39.147 67.2,38.777 67.4,38.6 67.206,37.669 66.947,37.416 66.688,37.162 66.428,36.908 66.169,36.654 R_I2C_SDA.2 66.281,36.4 66.652,36.4 67.023,36.4 67.232,36.191 67.441,35.982 67.65,35.773 67.656,35.773 v1(67.76,35.673) ; C_MCU_BULK.1@65.55,44.35 65.425,44.504 65.428,44.842 C_MCU_BULK.1 63.91,46.478 R_MCU_RESET.2 ; J_SENSOR_IO.1 63.91,57.3 R_MCU_RESET.2 ; v1(68.6,35.303) 68.813,35.303 69.087,35.577 69.361,35.852 69.636,36.126 R_I2C_SCL.2 76.91,36.4 R_SENSOR_CS.2 79.15,38.158 79.39,37.917 79.631,37.675 79.871,37.433 80.235,37.433 80.599,37.432 80.963,37.432 81.327,37.431 82.8,37.2 83.148,37.428 83.512,37.428 83.775,37.697 84.039,37.966 84.039,38.35 84.039,38.734 84.039,39.118 84.039,39.502 84.039,39.887 84.039,40.271 84.039,40.655 84.039,41.039 84.039,41.423 84.039,41.807 84.039,42.191 84.2,42.6 84.2,44 84.039,44.112 84.039,44.496 84.039,44.88 84.039,45.264 84.039,45.648 83.695,45.648 83.351,45.648 83.007,45.648 82.404,45.134 82.18,44.876 81.9,44.65 ; C_SENSOR_VDD.1 78.061,48.571 78.233,48.743 78.2,49.6 79.129,50.159 79.369,50.159 v1(79.609,50.159) ; v1(81.055,49.329) 81.147,49.237 81.147,49.223 81.361,49.009 81.575,48.795 C_SENSOR_BULK.1 ; U_SENSOR.5@81.76,44.465 81.575,44.65 C_SENSOR_BULK.1 ; C_SENSOR_VDDIO.1 85.629,48.661 85.369,48.921 85.108,49.182 84.848,49.442 84.587,49.703 84.327,49.963 84.066,50.224 83.712,50.225 83.358,50.227 83.003,50.229 82.649,50.23 81.8,50.4 81.4,50 81.27,49.551 81.3,49.3 81.392,49 81.483,48.7 C_SENSOR_BULK.1
  Bottom w0.3: 79.6,49.45 79.8,49.15 80,49.15 80.2,49.15
  Bottom w0.312: 79.6,49.45 79.604,49.805 v1(79.609,50.159) ; 80.2,49.15 80.35,49.3 80.5,49.45
  Bottom w0.4: v1(45.001,58.839) 45.036,58.913 45.036,58.971 45.177,59.111 45.179,59.397 v1(45.182,59.683) ; v1(46.369,36.243) 46.658,36.2 46.904,36.446 47.15,36.693 47.396,36.939 47.643,37.185 47.889,37.431 47.889,37.489 v1(48,37.6) ; J_SWD.1 52.86,57.606 52.925,57.542 52.925,57.527 v1(52.988,57.464) ; v1(57.476,57.215) 63.825,57.215 J_SENSOR_IO.1 ; v1(67.76,35.673) 68.042,35.669 68.207,35.504 68.372,35.339 68.564,35.339 v1(68.6,35.303) ; 80.5,49.45 80.47,49.836 80.502,50.221 80.534,50.607 80.566,50.993 80.598,51.379 80.63,51.764 80.765,51.642 80.91,51.294 81.055,50.947 81.055,50.623 81.055,50.3 81.055,49.976 81.055,49.653 v1(81.055,49.329)
pads on no net: J_SWD.6 J_SWD.7 J_SWD.8 J_USB.5 J_USB.11 J_USB.NPTH-1 J_USB.NPTH-2 U_LDO.4 U_MAIN.1 U_MAIN.2 U_MAIN.3 U_MAIN.4 U_MAIN.5 U_MAIN.6 U_MAIN.7 U_MAIN.8 U_MAIN.9 U_MAIN.10 U_MAIN.11 U_MAIN.14 U_MAIN.15 U_MAIN.16 U_MAIN.17 U_MAIN.18 U_MAIN.19 U_MAIN.20 U_MAIN.21 U_MAIN.22 U_MAIN.23 U_MAIN.24 U_MAIN.25 U_MAIN.26 U_MAIN.27 U_MAIN.28 U_MAIN.29 U_MAIN.30 U_MAIN.31 U_MAIN.33 U_MAIN.34 U_MAIN.35 U_MAIN.36 U_MAIN.37 U_MAIN.39 U_MAIN.43 U_MAIN.44 U_MAIN.45 U_MAIN.46 U_MAIN.49 U_MAIN.52 U_MAIN.53 U_MAIN.54 U_MAIN.55 U_MAIN.58 U_MAIN.59 U_MAIN.60 U_MAIN.61 U_MAIN.62 U_MAIN.63 U_MAIN.64 U_SENSOR.9 U_SENSOR.10 U_SENSOR.11 U_USB_UART.4
copper on no net:
  other v2: 37.2,44.4

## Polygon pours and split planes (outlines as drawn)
GND on Bottom (solid): 93.1,65.1 25.7,65.1 25.7,50.296 25.725,50.326 25.854,50.432 26.001,50.51 26.16,50.559 26.326,50.575 26.476,50.575 26.476,50.325 26.326,50.325 26.209,50.314 26.096,50.279 25.993,50.224 25.902,50.149 25.827,50.058 25.772,49.955 25.747,49.875 25.7,49.875 25.7,49.575 25.747,49.575 25.772,49.496 25.827,49.392 25.902,49.301 25.993,49.226 26.096,49.171 26.209,49.137 26.326,49.125 26.476,49.125 26.476,48.875 26.326,48.875 26.16,48.891 26.001,48.94 25.854,49.018 25.725,49.124 25.7,49.154 25.7,41.646 25.725,41.676 25.854,41.782 26.001,41.86 26.16,41.909 26.326,41.925 26.476,41.925 26.476,41.675 26.326,41.675 26.209,41.663 26.096,41.629 25.993,41.574 25.902,41.499 25.827,41.408 25.772,41.304 25.747,41.225 25.7,41.225 25.7,40.925 25.747,40.925 25.772,40.845 25.827,40.742 25.902,40.651 25.993,40.576 26.096,40.521 26.209,40.486 26.326,40.475 26.476,40.475 26.476,40.225 26.326,40.225 26.16,40.241 26.001,40.29 25.854,40.368 25.725,40.474 25.7,40.504 25.7,25.7 93.1,25.7
GND on Bottom (solid): 52.78,62.496 52.443,62.159 52.573,62.228 52.714,62.271 52.86,62.285 53.005,62.271
GND on Bottom (solid): 53.495,61.14 53.484,61.118 53.399,61.015 53.591,61.015 53.506,61.118
GND on Bottom (solid): 53.61,60.996 53.61,60.804 53.713,60.889 53.735,60.9 53.713,60.911
GND on Bottom (solid): 52.236,61.952 51.662,61.377 51.662,60.726 52.173,61.237 52.167,61.248 52.124,61.389 52.11,61.535 52.124,61.681 52.167,61.822
GND on Bottom (solid): 57.305,61.14 57.294,61.118 57.2,61.005 57.087,60.911 57.065,60.9 57.087,60.889 57.2,60.795 57.294,60.682 57.305,60.66 57.316,60.682 57.41,60.795 57.523,60.889 57.545,60.9 57.523,60.911 57.41,61.005 57.316,61.118
GND on Bottom (solid): 56.035,61.14 56.024,61.118 55.93,61.005 55.817,60.911 55.795,60.9 55.817,60.889 55.93,60.795 56.024,60.682 56.035,60.66 56.046,60.682 56.14,60.795 56.253,60.889 56.275,60.9 56.253,60.911 56.14,61.005 56.046,61.118
GND on Bottom (solid): 54.765,61.14 54.754,61.118 54.66,61.005 54.547,60.911 54.525,60.9 54.547,60.889 54.66,60.795 54.754,60.682 54.765,60.66 54.776,60.682 54.87,60.795 54.983,60.889 55.005,60.9 54.983,60.911 54.87,61.005 54.776,61.118

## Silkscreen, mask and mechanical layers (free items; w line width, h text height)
Top Overlay:
  text "3V3 • SWD • 2L" at 37.4,62.9 h0.48
  text "I2C 0x6A • USB-C UART" at 78.4,62.9 h0.5
  text "MSPM0G3507SPMR + CH340N" at 48.4,28.525 h0.52
  text "LSM6DSOXTR" at 81.4,28.525 h0.55
  text "QUICK CONFIGURE • SENSOR BOARD" at 64.4,27.9 h0.65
